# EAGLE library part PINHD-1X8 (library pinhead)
PIN HEADER
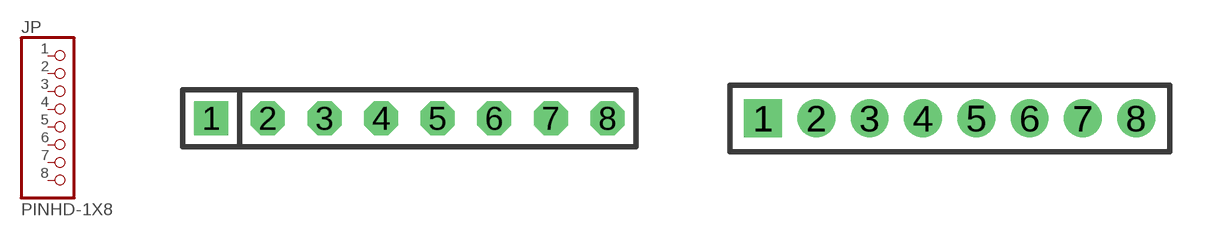
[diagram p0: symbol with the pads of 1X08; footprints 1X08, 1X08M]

Designator prefix JP

## PINHD-1X8  [1X08]
1  1  pas
2  2  pas
3  3  pas
4  4  pas
5  5  pas
6  6  pas
7  7  pas
8  8  pas

## PINHD-1X8M  [1X08M]
Pads as for 1X08

## Footprint 1X08 (pad centres in mm)
PIN HEADER - 0.1"
drill 1.016 square: 1 -8.89,0
drill 1.016 octagon: 2 -6.35,0; 3 -3.81,0; 4 -1.27,0; 5 1.27,0; 6 3.81,0; 7 6.35,0; 8 8.89,0

## Footprint 1X08M (pad centres in mm)
PIN HEADER - 2MM"
drill 0.914 square: 1 -7,0
drill 0.914 round: 2 -5,0; 3 -3,0; 4 -1,0; 5 1,0; 6 3,0; 7 5,0; 8 7,0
